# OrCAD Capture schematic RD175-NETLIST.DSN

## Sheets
1 5: size A3
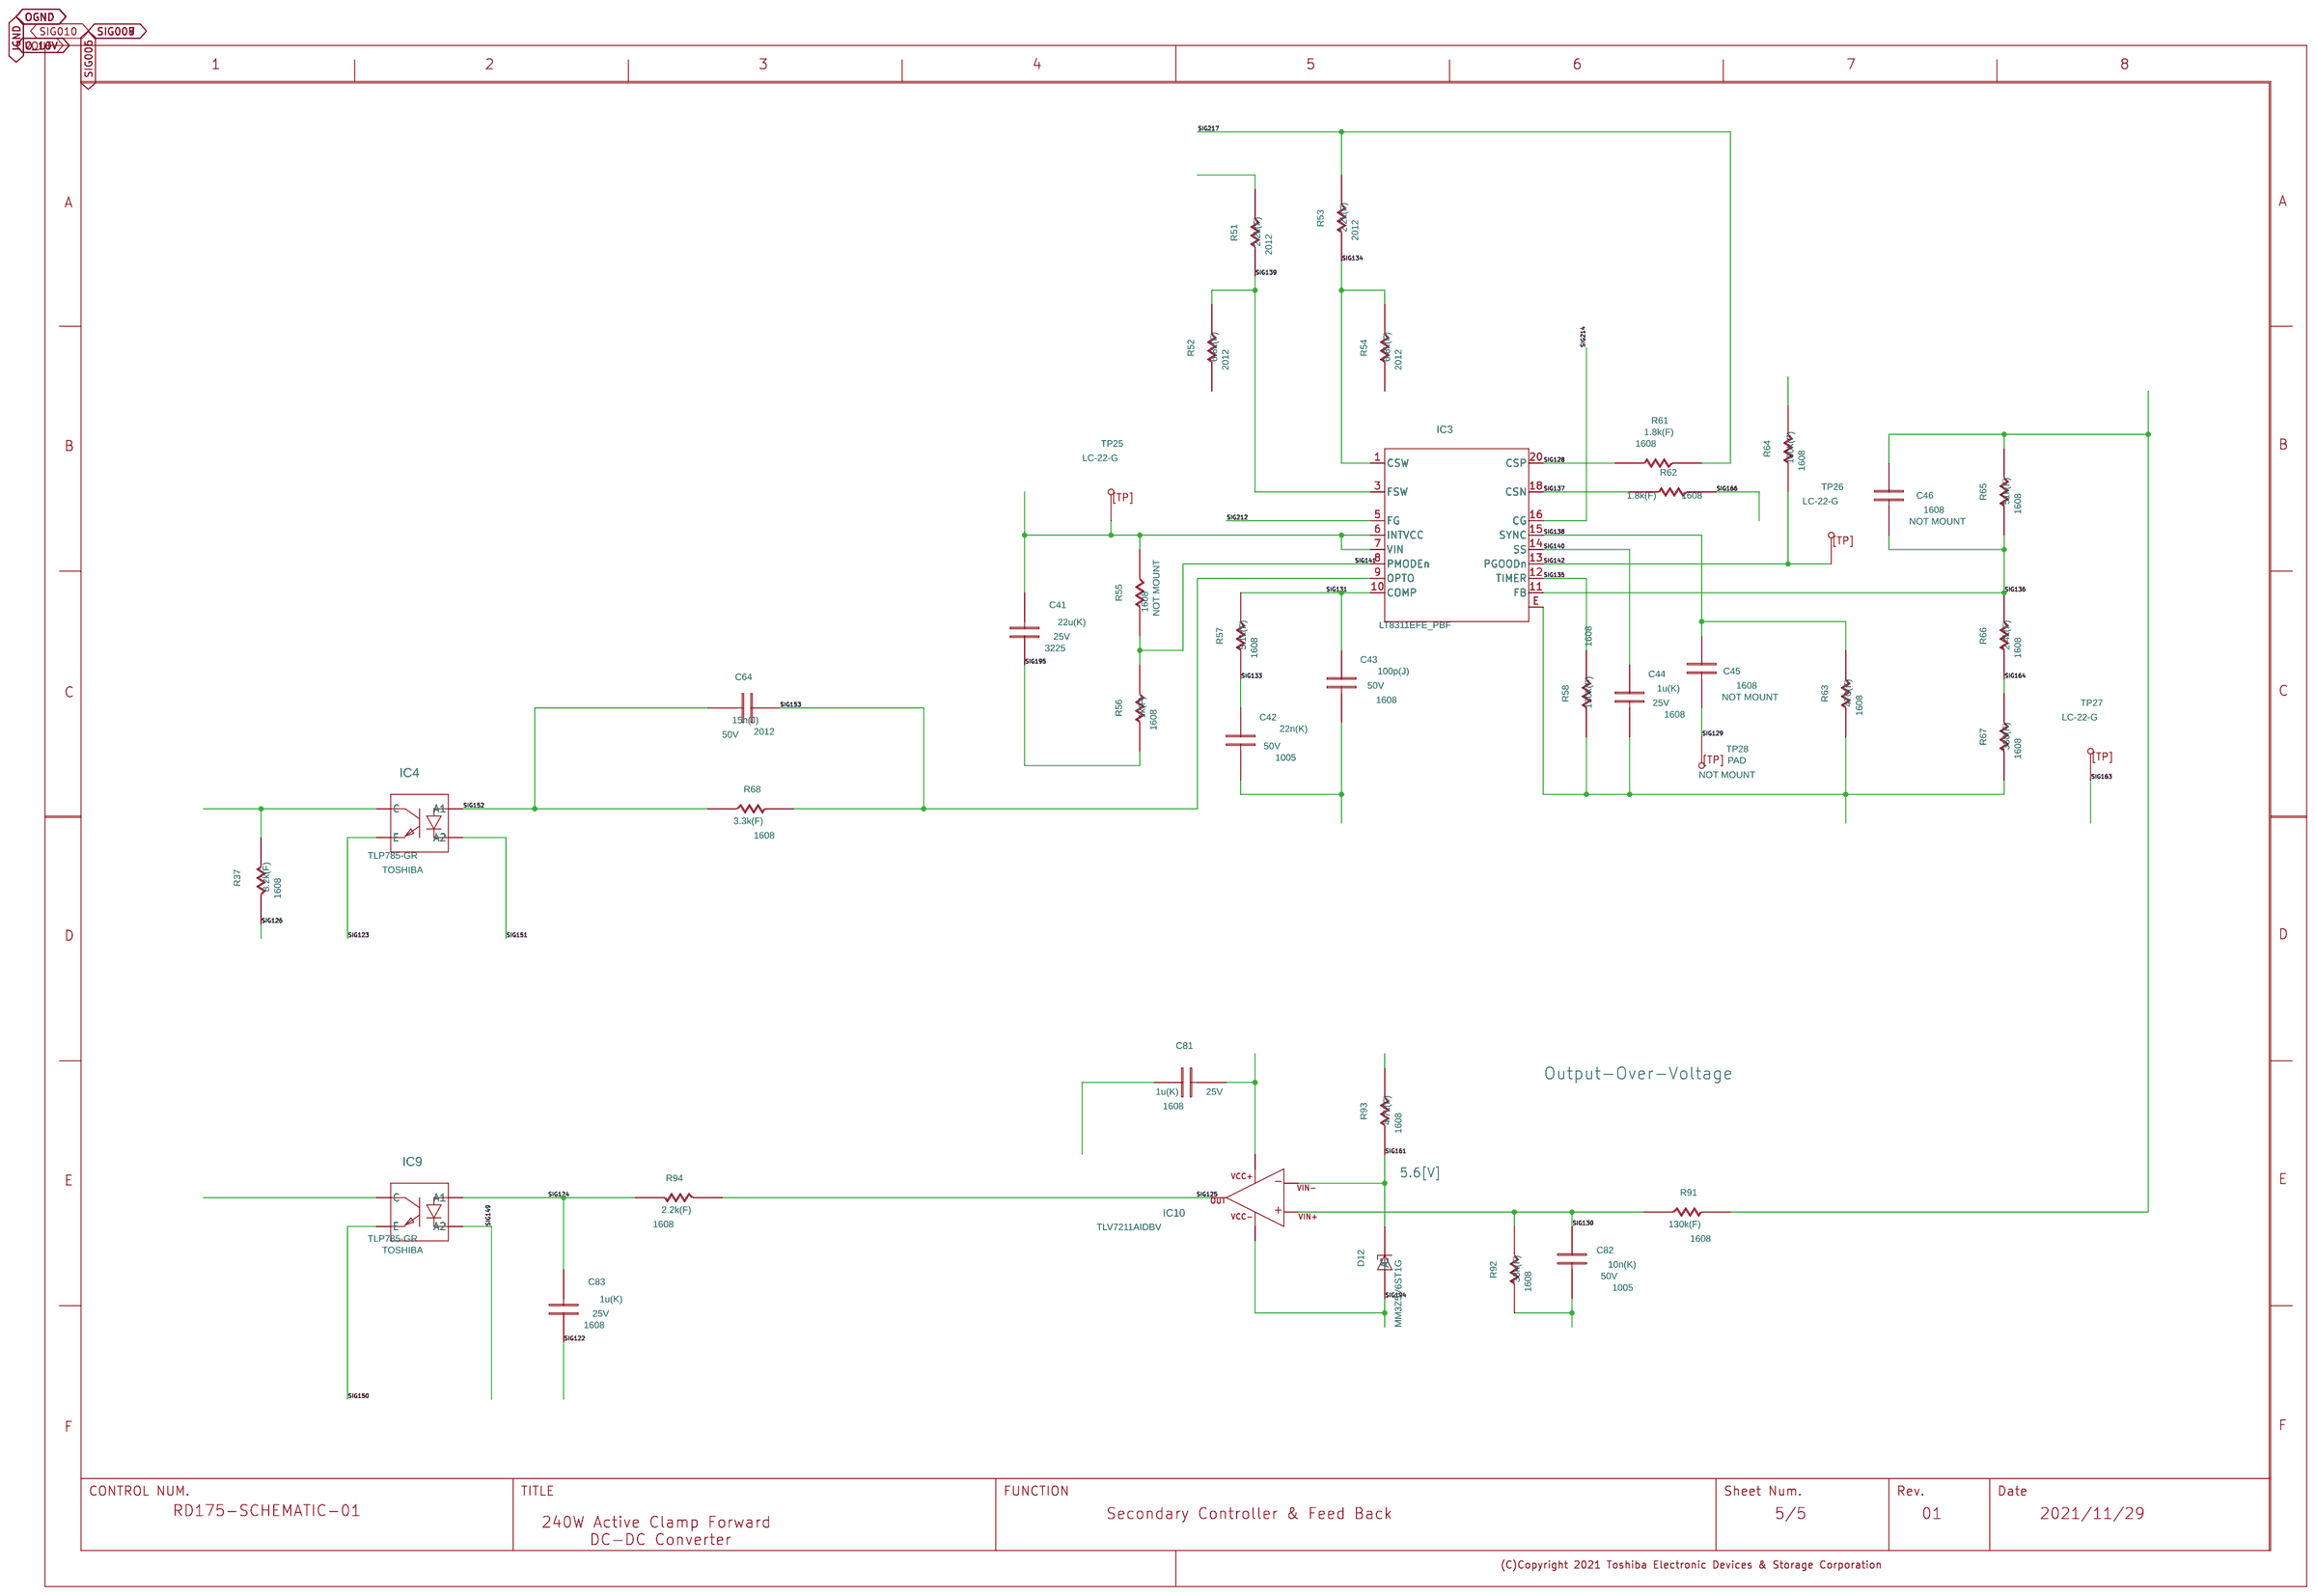
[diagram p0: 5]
2 4: size A3
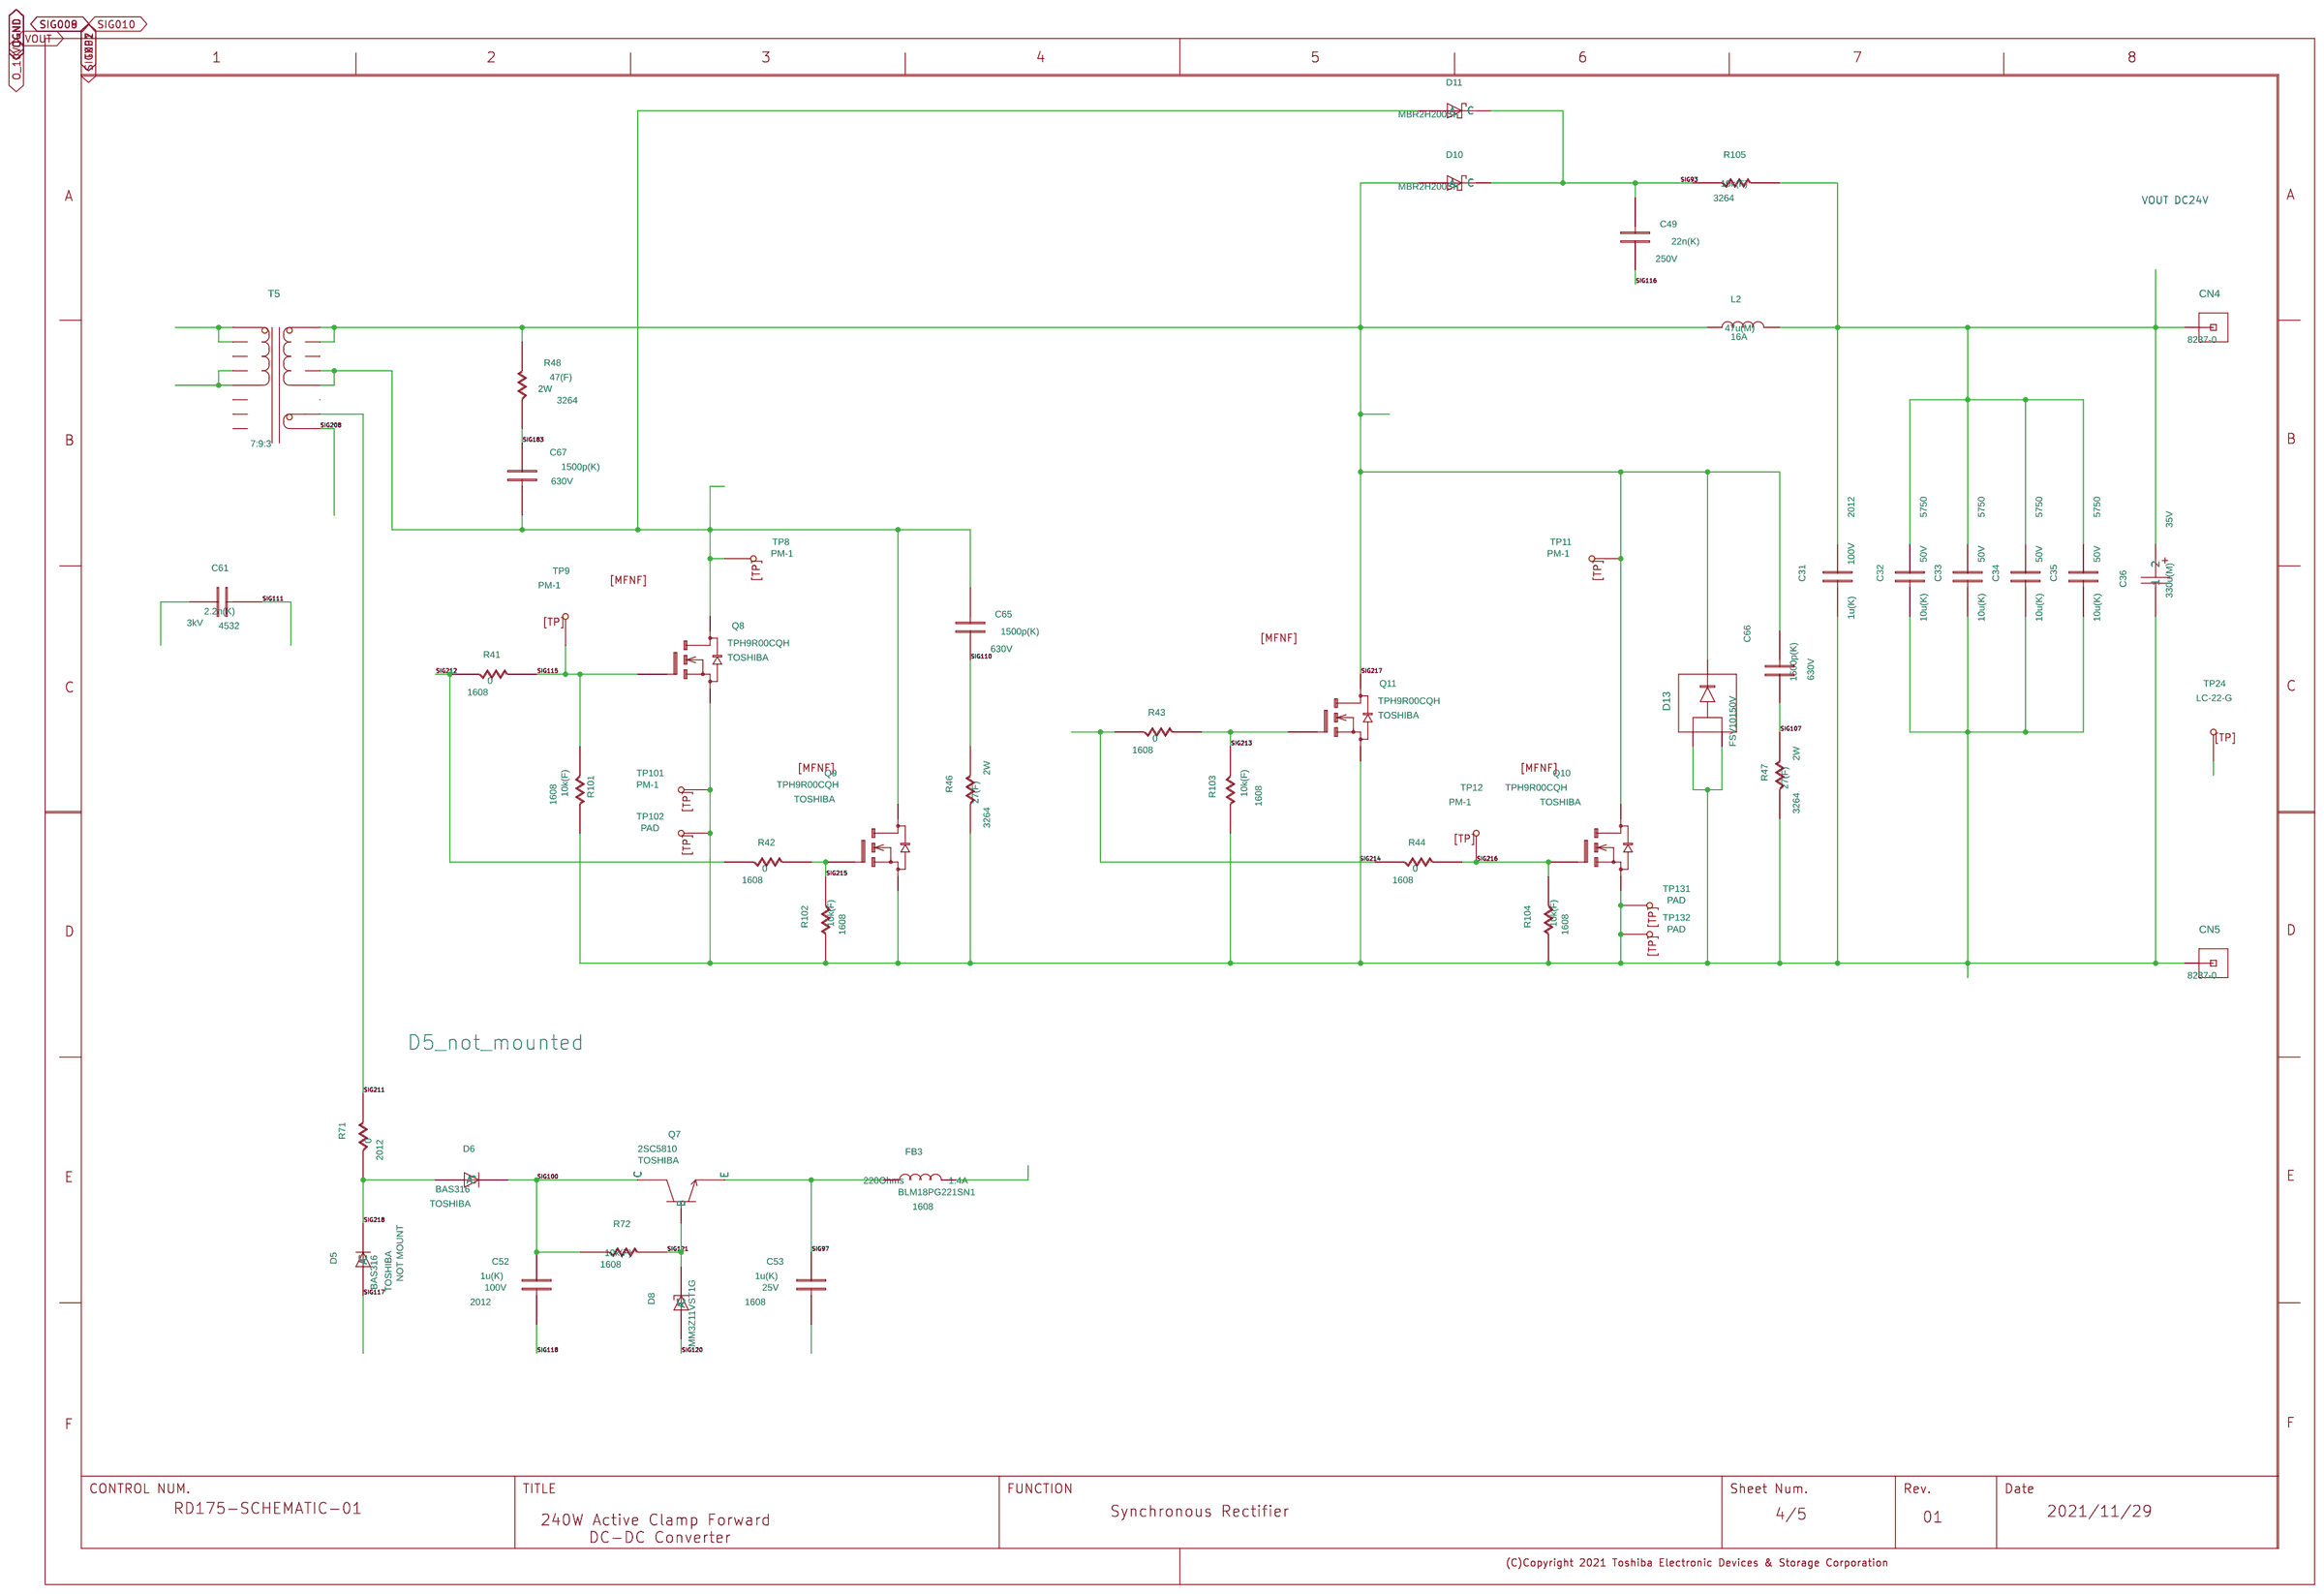
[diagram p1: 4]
3 3: size A3
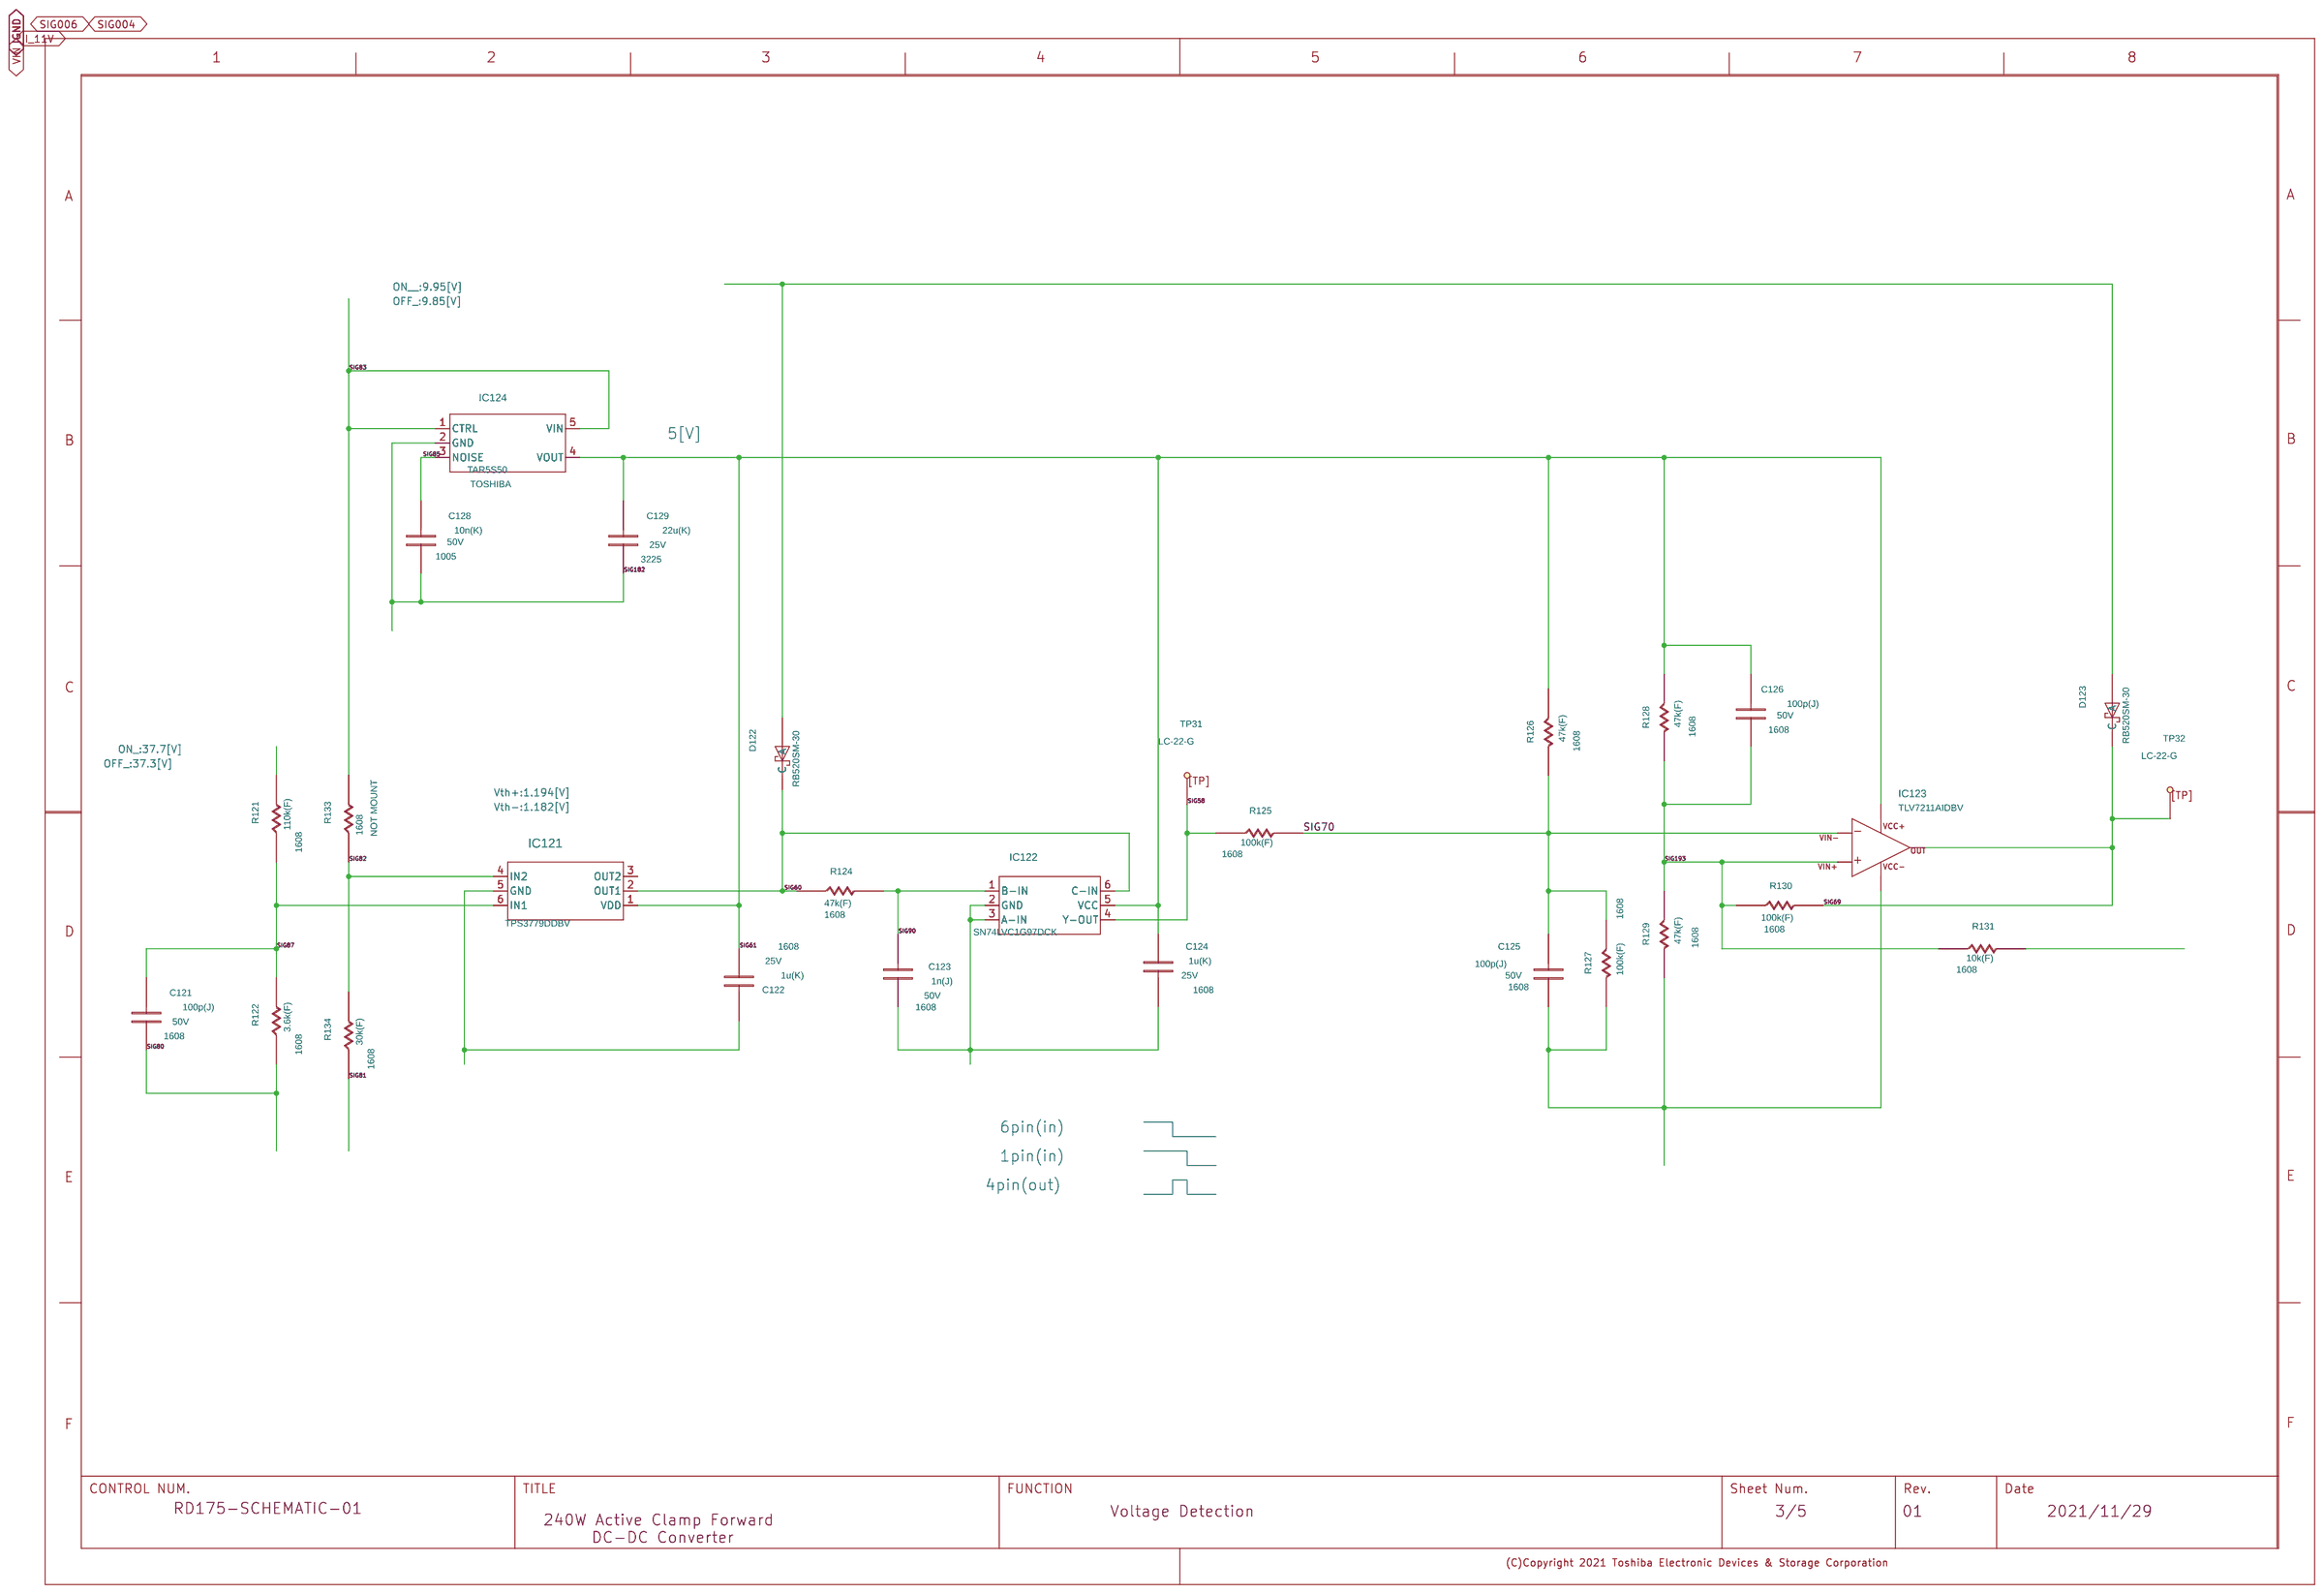
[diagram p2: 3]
4 2: size A3
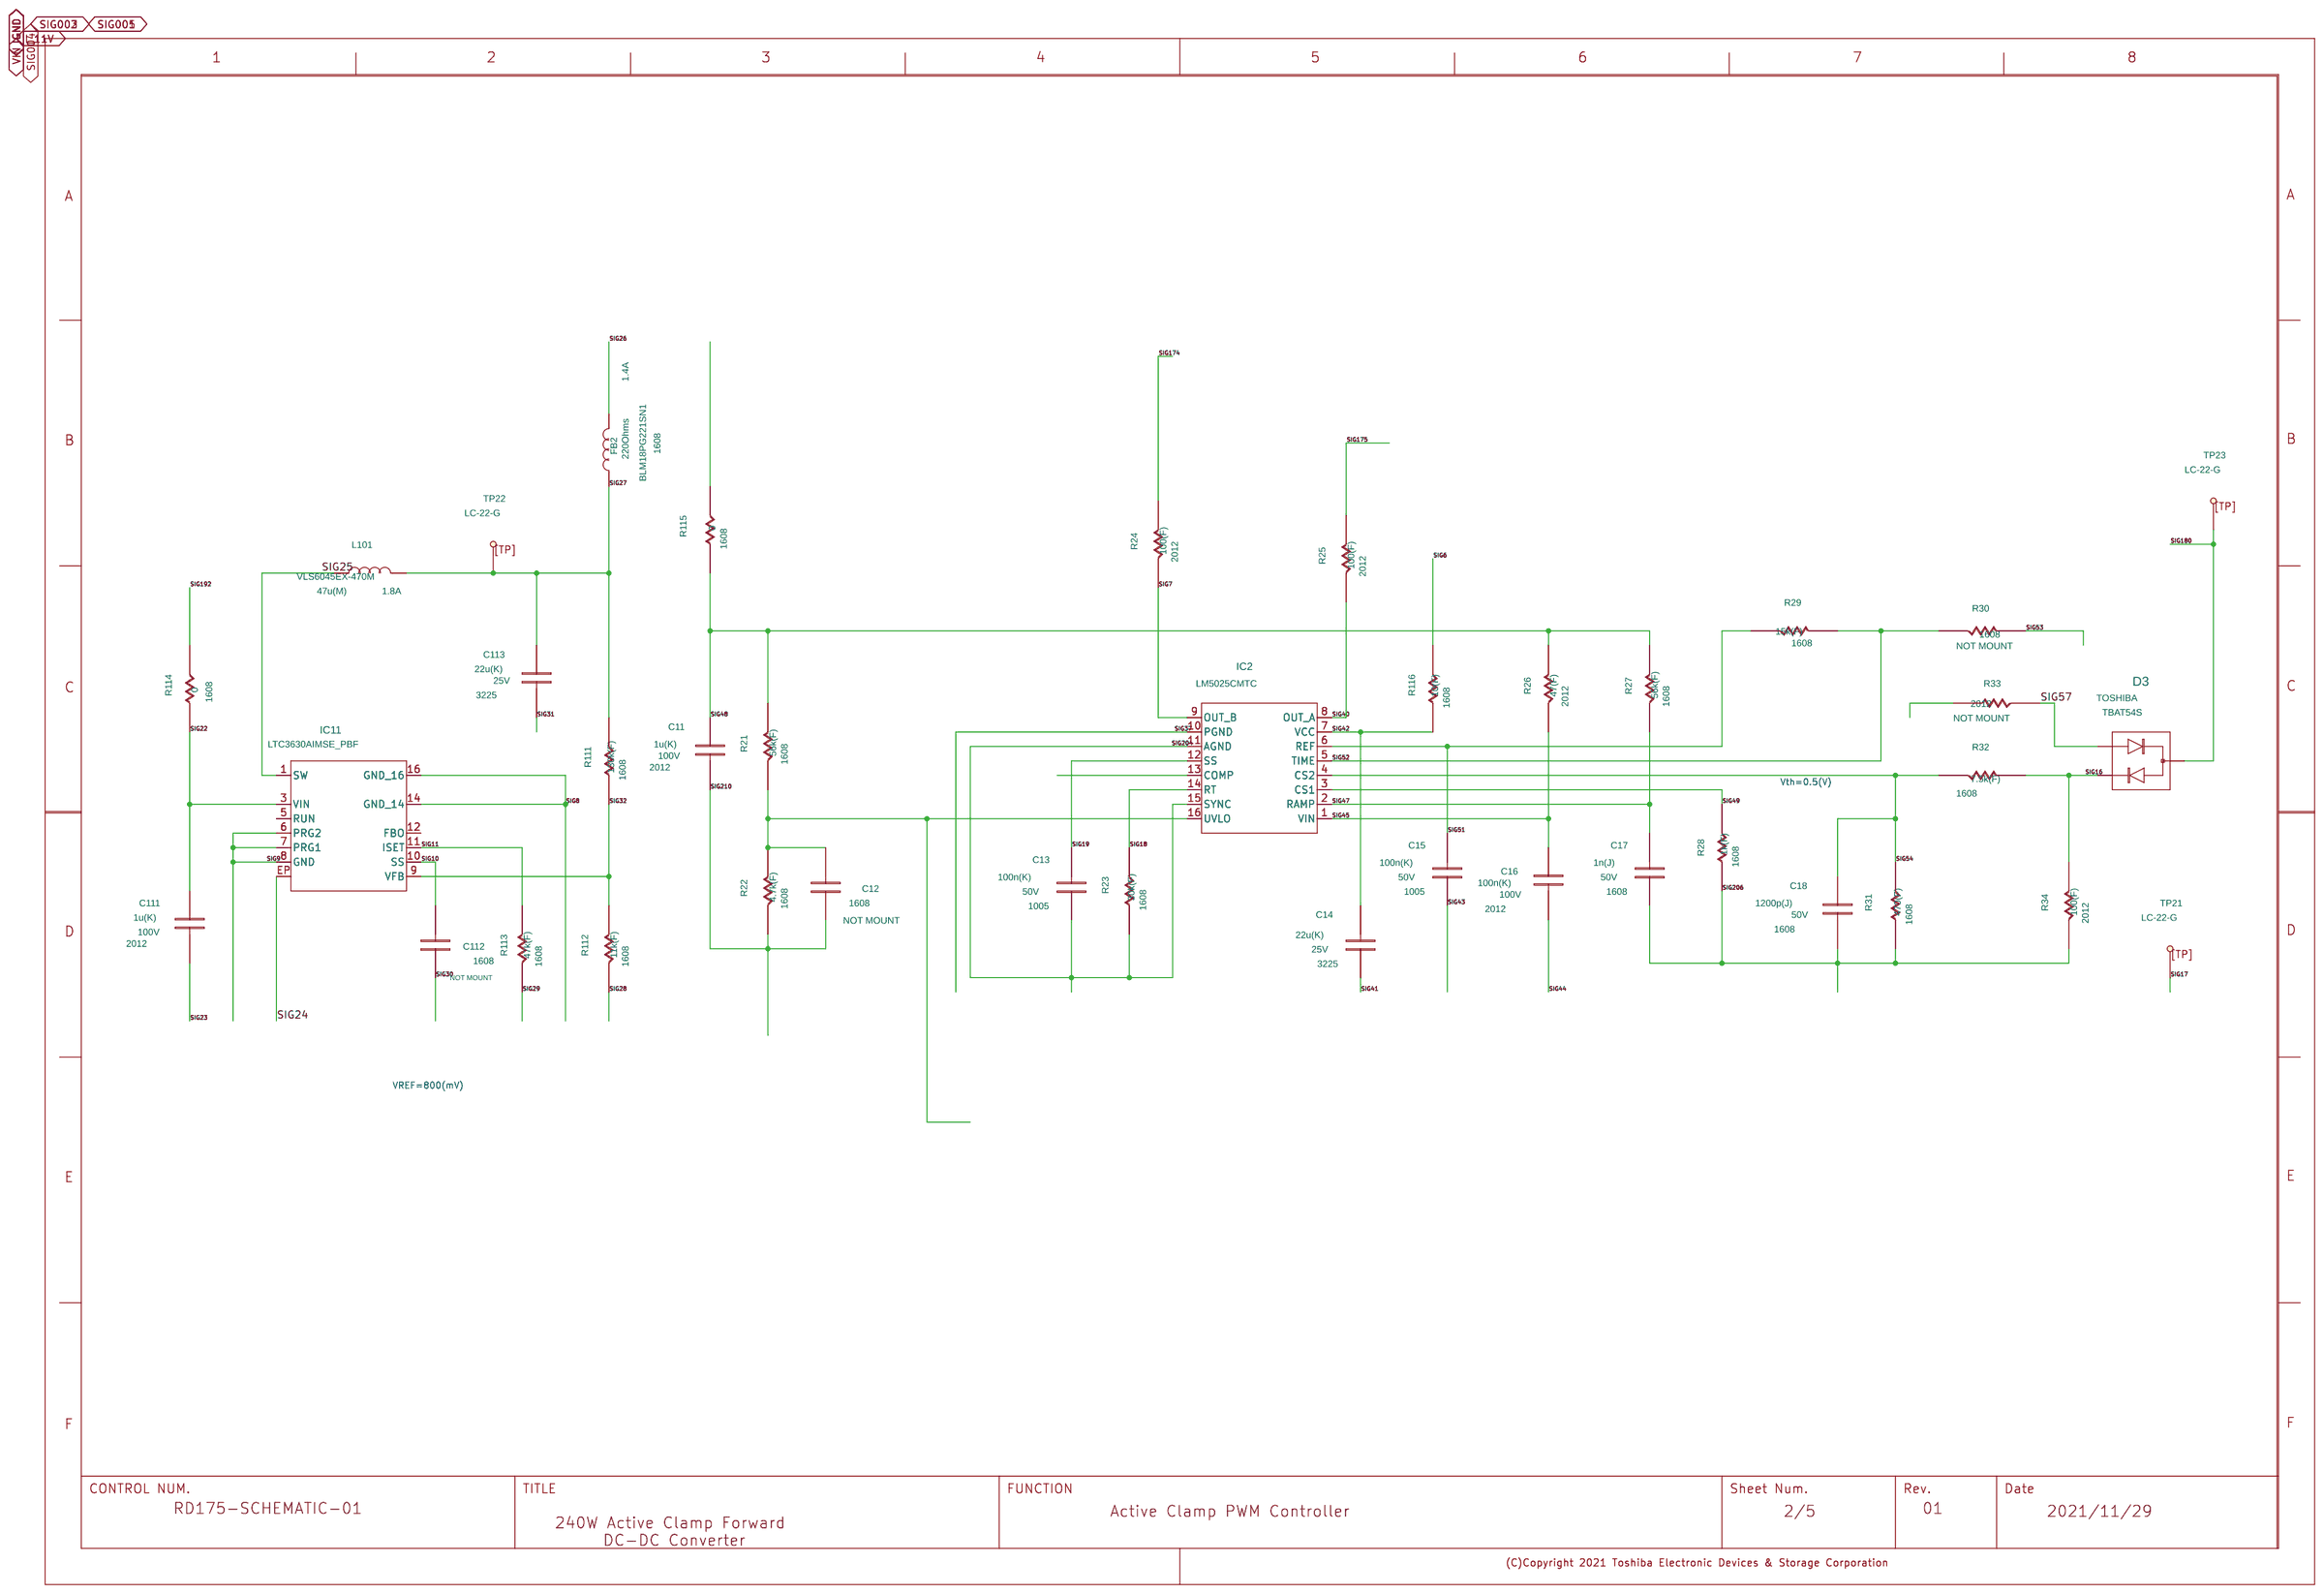
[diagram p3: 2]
5 1: size A3
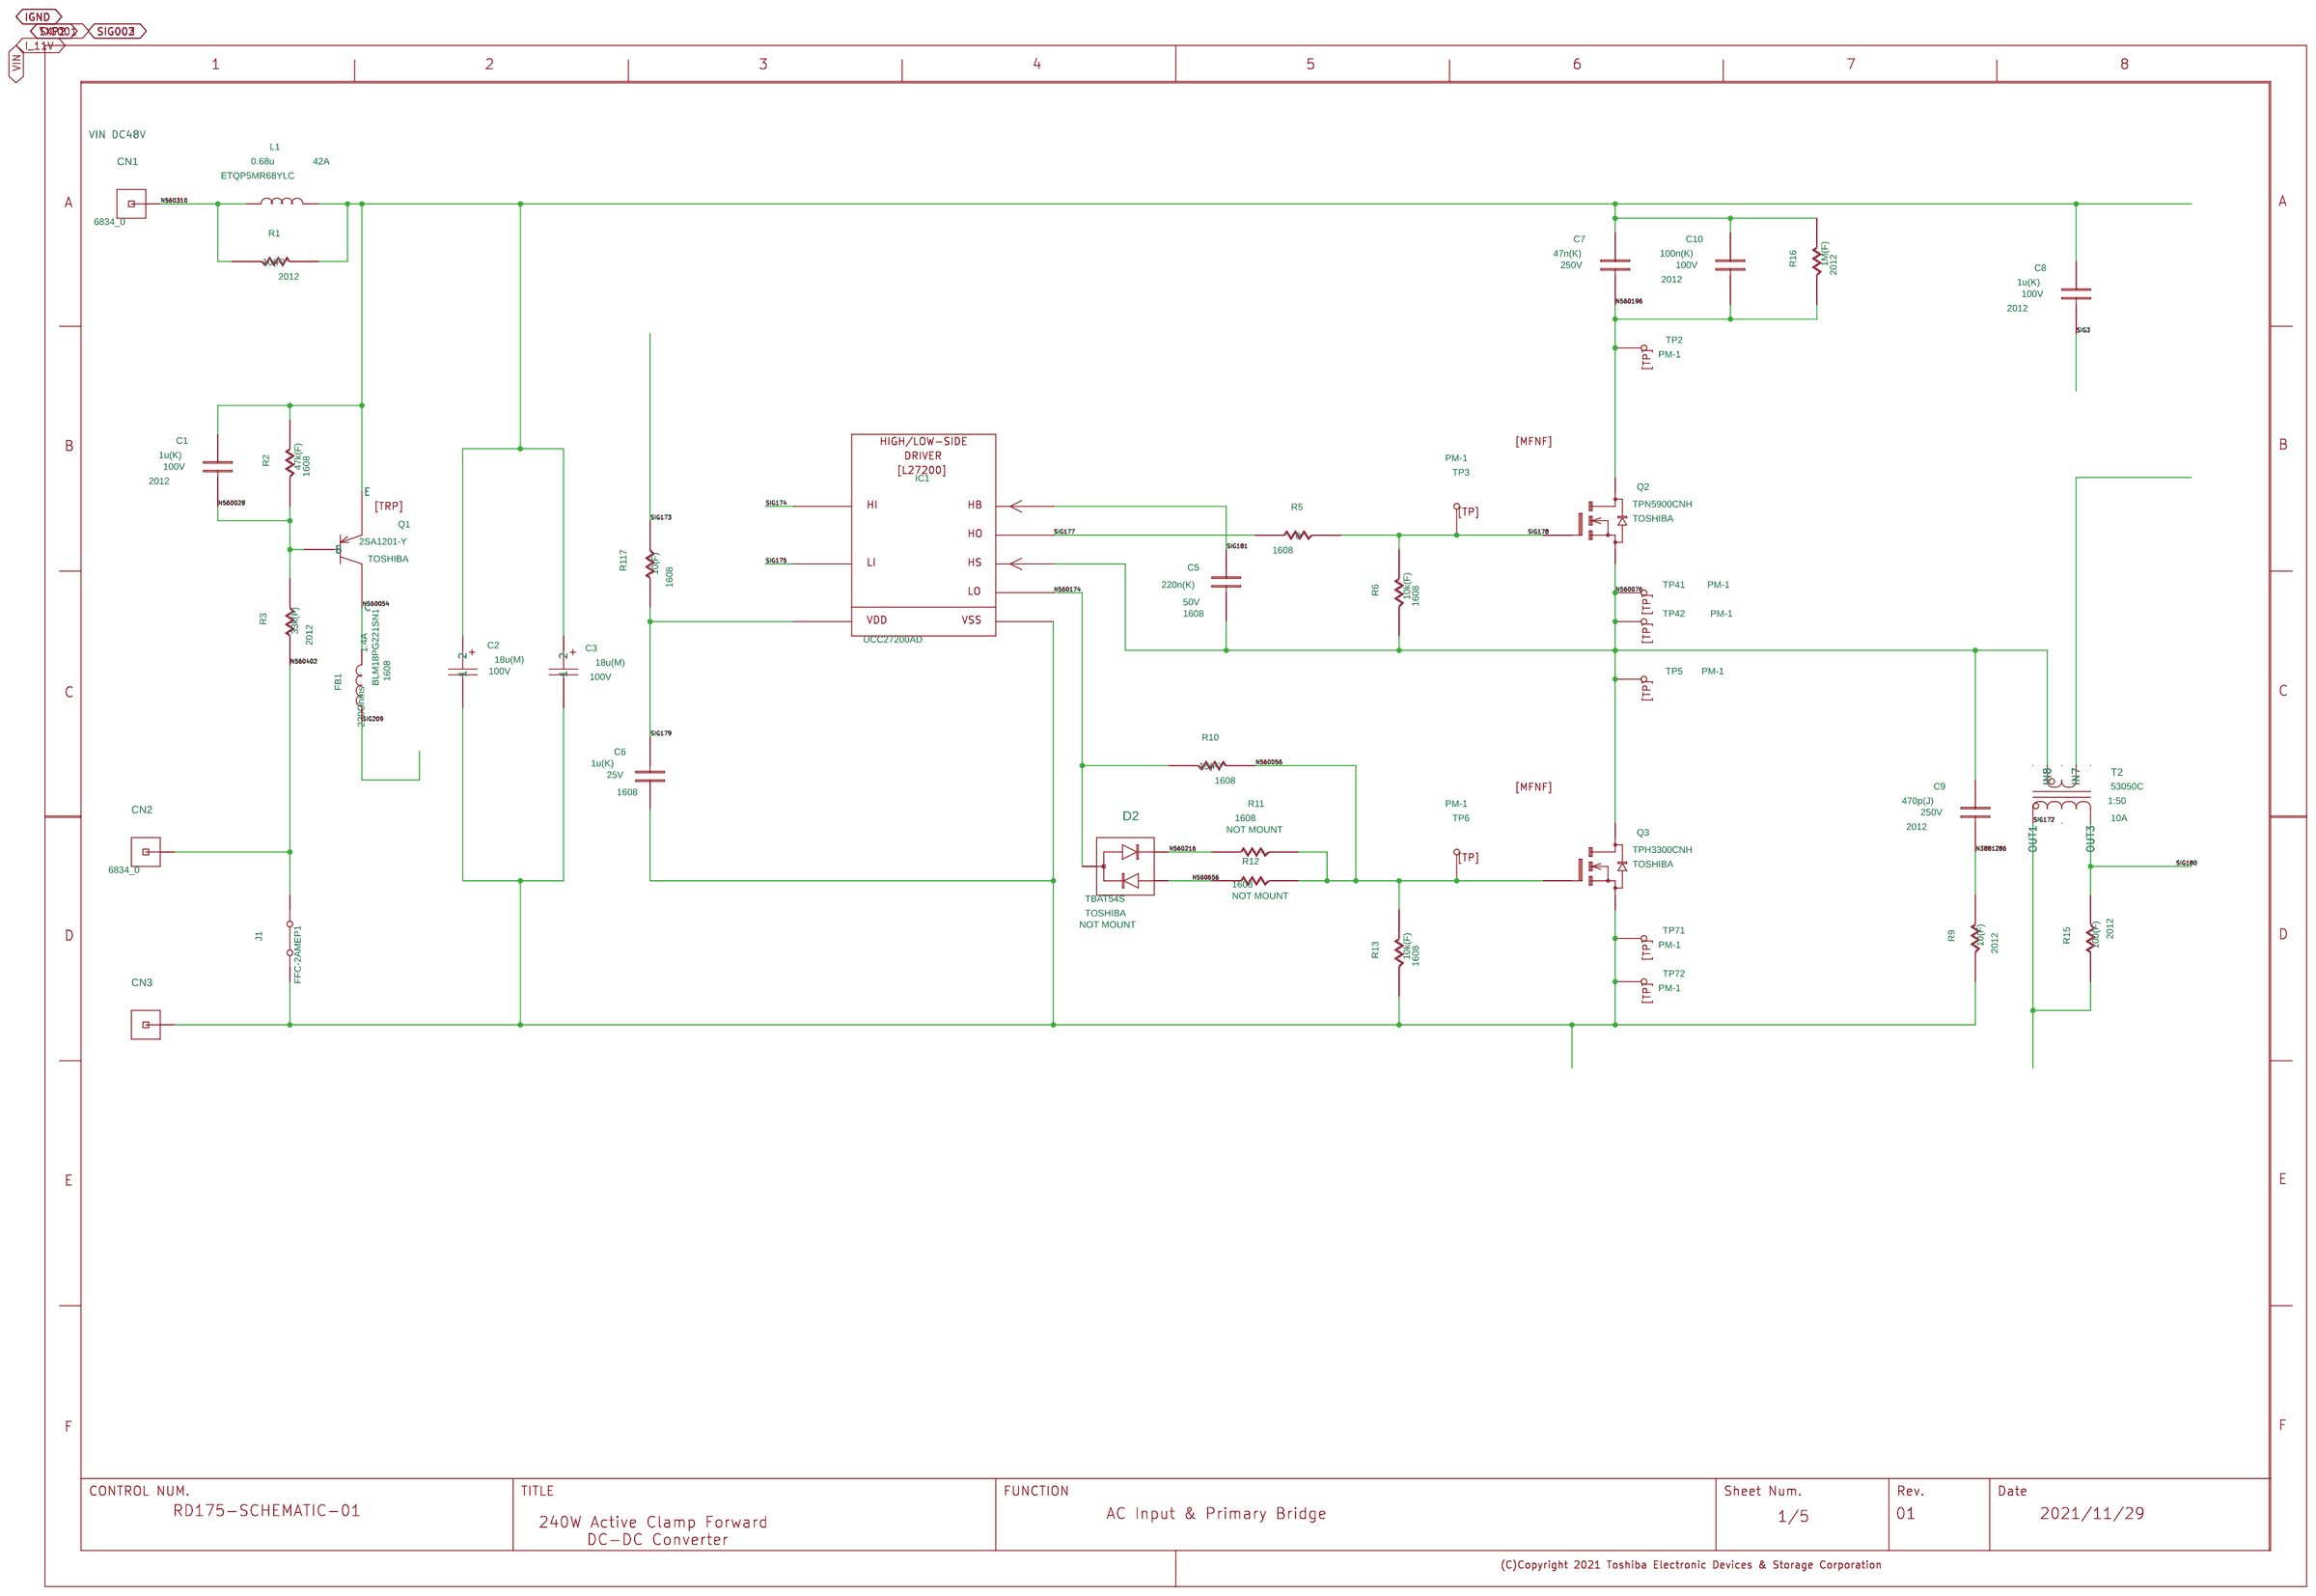
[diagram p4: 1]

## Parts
sheet 1
C1  C
C2  CP
C3  CP
C5  C
C6  C
C7  C
C8  C
C9  C
C10  C
CN1  6834-0  [TH-1]
CN2  6834-0  [TH-1]
CN3  6834-0  [TH-1]
D2  NM_TBAT54S  [SOT23-3]
FB1  L
IC1  L27200
J1  JP
L1  L
Q1  TRP
Q2  MFNF
Q3  MFNF
R1  R
R2  R
R3  R
R5  R
R6  R
R9  R
R10  R
R11  R
R12  R
R13  R
R15  R
R16  R
R117  R
T2  AF_TRANS_2B_MURATA_
TP2  TP
TP3  TP
TP5  TP
TP6  TP
TP41  TP
TP42  TP
TP71  TP
TP72  TP
U?#4  WAKU_DEF100
sheet 2
C11  C
C12  C
C13  C
C14  C
C15  C
C16  C
C17  C
C18  C
C111  C
C112  C
C113  C
D3  NM_TBAT54S  [SOT23-3]
FB2  L
IC2  LM5025C
IC11  LTC3630A
L101  L
R21  R
R22  R
R23  R
R24  R
R25  R
R26  R
R27  R
R28  R
R29  R
R30  R
R31  R
R32  R
R33  R
R34  R
R111  R
R112  R
R113  R
R114  R
R115  R
R116  R
TP21  TP
TP22  TP
TP23  TP
U?#3  WAKU_DEF100
sheet 3
C121  C
C122  C
C123  C
C124  C
C125  C
C126  C
C128  C
C129  C
D122  SBD
D123  SBD
IC121  TPS3779DDBV  [SOT23-6]
IC122  SN74AUP1G97_SMALL_
IC123  TLV7211A  [SOT23-5]
IC124  TAR5S50_NEW_
R121  R
R122  R
R124  R
R125  R
R126  R
R127  R
R128  R
R129  R
R130  R
R131  R
R133  R
R134  R
TP31  TP
TP32  TP
U?#2  WAKU_DEF100
sheet 4
C31  C
C32  C
C33  C
C34  C
C35  C
C36  CP
C49  C
C52  C
C53  C
C61  C
C65  C
C66  C
C67  C
CN4  8237-0  [TH-1]
CN5  8237-0  [TH-1]
D5  D
D6  D
D8  ZD
D10  SBD
D11  SBD
D13  Diode
FB3  L
L2  L
Q7  TRN
Q8  MFNF
Q9  MFNF
Q10  MFNF
Q11  MFNF
R41  R
R42  R
R43  R
R44  R
R46  R
R47  R
R48  R
R71  R
R72  R
R101  R
R102  R
R103  R
R104  R
R105  R
T5  AF_TRANS_4B_
TP8  TP
TP9  TP
TP11  TP
TP12  TP
TP24  TP
TP101  TP
TP102  TP
TP131  TP
TP132  TP
U?#1  WAKU_DEF100
sheet 5
C41  C
C42  C
C43  C
C44  C
C45  C
C46  C
C64  C
C81  C
C82  C
C83  C
D12  ZD
IC3  LT8311
IC4  TLP785-GR  [DIP-4]
IC9  TLP785-GR  [DIP-4]
IC10  OP_AMP_5PIN_2_
R37  R
R51  R
R52  R
R53  R
R54  R
R55  R
R56  R
R57  R
R58  R
R61  R
R62  R
R63  R
R64  R
R65  R
R66  R
R67  R
R68  R
R91  R
R92  R
R93  R
R94  R
TP25  TP
TP26  TP
TP27  TP
TP28  TP
U?#5  WAKU_DEF100

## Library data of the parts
C1 C8 C11 C31 C52 C111 = C: CDBNAME: Chip2012_GS_1; COMP: Chip2012_GS_1; COMPONENTTYPE: 4; SIZECODESMD: 2012; VAL1: 1u(K); VAL2: 100V
C2 C3 = CP: CDBNAME: PCV2A180MCL1_NC; COMP: PCV2A180MCL1_NC; COMPONENTTYPE: 4; VAL1: 18u(M); VAL2: 100V
C5 = C: CDBNAME: Chip1608_GS_1; COMP: Chip1608_GS_1; COMPONENTTYPE: 4; SIZECODESMD: 1608; VAL1: 220n(K); VAL2: 50V
C6 = C: CDBNAME: Chip1608_GS_1; COMP: Chip1608_GS_1; COMPONENTTYPE: 4; OLDCOMPONENTID: 311; SIZECODESMD: 1608; VAL1: 1u(K); VAL2: 25V
C7 = C: CDBNAME: ECQE2224*F_PN; COMP: ECQE2224*F_PN; COMPONENTTYPE: 4; VAL1: 47n(K); VAL2: 250V
C9 = C: CDBNAME: Chip2012_GS_1; COMP: Chip2012_GS_1; COMPONENTTYPE: 4; SIZECODESMD: 2012; VAL1: 470p(J); VAL2: 250V
C10 C16 = C: CDBNAME: Chip2012_GS_1; COMP: Chip2012_GS_1; COMPONENTTYPE: 4; SIZECODESMD: 2012; VAL1: 100n(K); VAL2: 100V
CN1 CN2 = TESTPIN_SHORT: CDBNAME: 6834-0-00-**-00-00-03-0_ML; COMMENT: Press-fit-Pin; COMP: 6834-0-00-**-00-00-03-0_ML; COMPONENTTYPE: 4; INSTANCENAME: I582755; MAKER: Mill-Max; SAVECOUNT: 1; TYPE: 6834-0-00-15-00-00-03-0; UPDATEDATE: 2021/11/09; UPDATETIME: 20:28:41; VAL1: 6834_0; VAL3: 6834_0
CN3 = TESTPIN_SHORT: CDBNAME: 6834-0-00-**-00-00-03-0_ML; COMMENT: Press-fit-Pin; COMP: 6834-0-00-**-00-00-03-0_ML; COMPONENTTYPE: 4; INSTANCENAME: I580723; MAKER: Mill-Max; SAVECOUNT: 1; TYPE: 6834-0-00-15-00-00-03-0; UPDATEDATE: 2021/11/09; UPDATETIME: 20:28:41; VAL1: 6834_0; VAL3: 6834_0
D2 = 1SS226: CDBNAME: TBAT54S_TS; COMMENT: Schottky-barrier-diode(Dual,30V200mA); COMP: TBAT54S_TS; COMPONENTTYPE: 4; INSTANCENAME: I582211; MAKER: Toshiba; MOUNT: n.m.; NOTMOUNT: NOT MOUNT; TYPE: TBAT54S; USERCOMPTEXT3: TOSHIBA; VAL1: TBAT54S; VAL3: TBAT54S
FB1-FB3 = L: CDBNAME: Chip1608_GS_1; COMP: Chip1608_GS_1; COMPONENTTYPE: 4; SIZECODESMD: 1608; VAL1: 220Ohms; VAL2: 1.4A; VAL3: BLM18PG221SN1
IC1 = L27200: CDBNAME: UCC272**AD_TI; COMP: UCC272**AD_TI; COMPONENTTYPE: 4; VAL1: UCC27200AD; VAL3: UCC27200AD
J1 = JP: CDBNAME: FFC-2AMEP1_HN; COMP: FFC-2AMEP1_HN; COMPONENTTYPE: 4; VAL1: FFC-2AMEP1; VAL3: FFC-2AMEP1
L1 = L: CDBNAME: ETQP5M***YLC_PN; COMP: ETQP5M***YLC_PN; COMPONENTTYPE: 4; VAL1: 0.68u; VAL2: 42A; VAL3: ETQP5MR68YLC
Q1 = TRP: CDBNAME: 2SA1201_TS; COMP: 2SA1201_TS; COMPONENTTYPE: 4; USERCOMPTEXT3: TOSHIBA; VAL1: 2SA1201-Y; VAL3: 2SA1201-Y
Q2 = MFNF: CDBNAME: TPN5900CNH_TS; COMP: TPN5900CNH_TS; COMPONENTTYPE: 4; USERCOMPTEXT3: TOSHIBA; VAL1: TPN5900CNH; VAL3: TPN5900CNH
Q3 = MFNF: CDBNAME: TPH3300CNH_TS_A; COMP: TPH3300CNH_TS_A; COMPONENTTYPE: 4; USERCOMPTEXT3: TOSHIBA; VAL1: TPH3300CNH; VAL3: TPH3300CNH
R1 R9 = R: CDBNAME: Chip2012_GS_2; COMP: Chip2012_GS_2; COMPONENTTYPE: 4; SIZECODESMD: 2012; VAL1: 10(F); VAL2: 400mW
R2 R113 R126 R128 R129 = R: CDBNAME: Chip1608_GS_1; COMP: Chip1608_GS_1; COMPONENTTYPE: 4; SIZECODESMD: 1608; VAL1: 47k(F); VAL2: 100mW
R3 = R: CDBNAME: Chip2012_GS_2; COMP: Chip2012_GS_2; COMPONENTTYPE: 4; SIZECODESMD: 2012; VAL1: 33k(F); VAL2: 400mW
R5 R41-R44 R114 R115 = R: CDBNAME: Chip1608_GS_1; COMP: Chip1608_GS_1; COMPONENTTYPE: 4; SIZECODESMD: 1608; VAL1: 0
R6 R13 R72 R101-R104 R131 = R: CDBNAME: Chip1608_GS_1; COMP: Chip1608_GS_1; COMPONENTTYPE: 4; SIZECODESMD: 1608; VAL1: 10k(F); VAL2: 100mW
R10 = R: CDBNAME: Chip1608_GS_1; COMP: Chip1608_GS_1; COMPONENTTYPE: 4; SIZECODESMD: 1608; VAL1: 15(F); VAL2: 100mW
R11 R12 = R: CDBNAME: Chip1608_GS_1; COMP: Chip1608_GS_1; COMPONENTTYPE: 4; NOTMOUNT: NOT MOUNT; SIZECODESMD: 1608; VAL1: 10(F); VAL2: 100mW
R15 R24 R25 R34 = R: CDBNAME: Chip2012_GS_2; COMP: Chip2012_GS_2; COMPONENTTYPE: 4; SIZECODESMD: 2012; VAL1: 100(F); VAL2: 400mW
R16 = R: CDBNAME: Chip2012_GS_2; COMP: Chip2012_GS_2; COMPONENTTYPE: 4; SIZECODESMD: 2012; VAL1: 1M(F); VAL2: 400mW
R116 R117 = R: CDBNAME: Chip1608_GS_1; COMP: Chip1608_GS_1; COMPONENTTYPE: 4; SIZECODESMD: 1608; VAL1: 10(F); VAL2: 100mW
T2 = AF_TRANS_2B_MURATA: CDBNAME: 53***C_MU; COMP: 53***C_MU; COMPONENTTYPE: 4; SAVEAREA0: -37891,-23575,42821,13630; SAVECOUNT: 2; UPDATEDATE: 2021/11/16; UPDATETIME: 15:26:59; VAL1: 1:50; VAL2: 10A; VAL3: 53050C
TP2 TP3 TP5 TP6 TP8 TP9 TP11 TP12 TP41 TP42 TP71 TP72 TP101 = TP: CDBNAME: TP_I_TH0.7_LC1.1_RC1.2_GS; COMP: TP_I_TH0.7_LC1.1_RC1.2_GS; COMPONENTTYPE: 4; VAL1: PM-1; VAL3: PM-1
U?#4 = WAKU_DEF100: COMPONENTTYPE: 2; DATE: 2021/11/29; DRAWINGNUMBER: RD175-SCHEMATIC-01; FUNCTION: AC Input & Primary Bridge; REVISION: 01; SHEETNUMBER: 1/5; TITLE: 240W Active Clamp Forward / DC-DC Converter; UPDATEDATE: 2021/11/29; UPDATETIME: 13:17:36
C12 C112 = C: CDBNAME: Chip1608_GS_1; COMP: Chip1608_GS_1; COMPONENTTYPE: 4; NOTMOUNT: NOT MOUNT; SIZECODESMD: 1608; VAL1: 1n(J); VAL2: 50V
C13 C15 = C: CDBNAME: Chip1005_GS_2; COMP: Chip1005_GS_2; COMPONENTTYPE: 4; SIZECODESMD: 1005; VAL1: 100n(K); VAL2: 50V
C14 C41 C113 C129 = C: CDBNAME: Chip3225_GS; COMP: Chip3225_GS; COMPONENTTYPE: 4; SIZECODESMD: 3225; VAL1: 22u(K); VAL2: 25V
C17 C123 = C: CDBNAME: Chip1608_GS_1; COMP: Chip1608_GS_1; COMPONENTTYPE: 4; SIZECODESMD: 1608; VAL1: 1n(J); VAL2: 50V
C18 = C: CDBNAME: Chip1608_GS_1; COMP: Chip1608_GS_1; COMPONENTTYPE: 4; SIZECODESMD: 1608; VAL1: 1200p(J); VAL2: 50V
D3 = 1SS226: CDBNAME: TBAT54S_TS; COMMENT: Schottky-barrier-diode(Dual,30V200mA); COMP: TBAT54S_TS; COMPONENTTYPE: 4; INSTANCENAME: I582211; MAKER: Toshiba; MOUNT: n.m.; TYPE: TBAT54S; USERCOMPTEXT3: TOSHIBA; VAL1: TBAT54S; VAL3: TBAT54S
IC2 = LM5025C: CDBNAME: LM5025CMTC_GS; COMP: LM5025CMTC_GS; COMPONENTTYPE: 4; SAVEAREA0: -6985,-23317,26564,1279; SAVECOUNT: 2; UPDATEDATE: 2021/11/12; UPDATETIME: 11:19:07; VAL1: LM5025CMTC; VAL3: LM5025CMTC
IC11 = LTC3630A: CDBNAME: LTC3630AIM_LT_1; COMP: LTC3630AIM_LT_1; COMPONENTTYPE: 4; VAL1: LTC3630AIMSE_PBF; VAL3: LTC3630AIMSE_PBF
L101 = L: CDBNAME: VLS6045EX_TD; COMP: VLS6045EX_TD; COMPONENTTYPE: 4; VAL1: 47u(M); VAL2: 1.8A; VAL3: VLS6045EX-470M
R21 R27 = R: CDBNAME: Chip1608_GS_1; COMP: Chip1608_GS_1; COMPONENTTYPE: 4; SIZECODESMD: 1608; VAL1: 56k(F); VAL2: 100mW
R22 R93 = R: CDBNAME: Chip1608_GS_1; COMP: Chip1608_GS_1; COMPONENTTYPE: 4; SIZECODESMD: 1608; VAL1: 4.7k(F); VAL2: 100mW
R23 R134 = R: CDBNAME: Chip1608_GS_1; COMP: Chip1608_GS_1; COMPONENTTYPE: 4; SIZECODESMD: 1608; VAL1: 30k(F); VAL2: 100mW
R26 = R: CDBNAME: Chip2012_GS_2; COMP: Chip2012_GS_2; COMPONENTTYPE: 4; SIZECODESMD: 2012; VAL1: 47(F); VAL2: 400mW
R28 R56 = R: CDBNAME: Chip1608_GS_1; COMP: Chip1608_GS_1; COMPONENTTYPE: 4; SIZECODESMD: 1608; VAL1: 1k(F); VAL2: 100mW
R29 = R: CDBNAME: Chip1608_GS_1; COMP: Chip1608_GS_1; COMPONENTTYPE: 4; SIZECODESMD: 1608; VAL1: 15k(F); VAL2: 100mW
R30 = R: CDBNAME: Chip1608_GS_1; COMP: Chip1608_GS_1; COMPONENTTYPE: 4; NOTMOUNT: NOT MOUNT; SIZECODESMD: 1608; VAL1: 15k(F); VAL2: 100mW
R31 R63 = R: CDBNAME: Chip1608_GS_1; COMP: Chip1608_GS_1; COMPONENTTYPE: 4; SIZECODESMD: 1608; VAL1: 470(F); VAL2: 100mW
R32 = R: CDBNAME: Chip1608_GS_1; COMP: Chip1608_GS_1; COMPONENTTYPE: 4; SIZECODESMD: 1608; VAL1: 7.5k(F); VAL2: 100mW
R33 = R: CDBNAME: Chip2012_GS_2; COMP: Chip2012_GS_2; COMPONENTTYPE: 4; NOTMOUNT: NOT MOUNT; SIZECODESMD: 2012; VAL1: 100(F); VAL2: 400mW
R58 R91 R111 = R: CDBNAME: Chip1608_GS_1; COMP: Chip1608_GS_1; COMPONENTTYPE: 4; SIZECODESMD: 1608; VAL1: 130k(F); VAL2: 100mW
R112 = R: CDBNAME: Chip1608_GS_1; COMP: Chip1608_GS_1; COMPONENTTYPE: 4; SIZECODESMD: 1608; VAL1: 11k(F); VAL2: 100mW
TP21-TP27 TP31 TP32 = TP: CDBNAME: LC-22_GS; COMP: LC-22_GS; COMPONENTTYPE: 4; VAL1: LC-22-G; VAL3: LC-22-G
U?#3 = WAKU_DEF100: AUTHOR: t5459927; COMPONENTTYPE: 2; DATE: 2021/11/29; DRAWINGNUMBER: RD175-SCHEMATIC-01; FUNCTION: Active Clamp PWM Controller; REVISION: 01; SAVEAREA0: -45080,-4508,463680,304612; SHEETNUMBER: 2/5; TIME: 14:24:20; TITLE: 240W Active Clamp Forward / DC-DC Converter; UPDATEDATE: 2021/11/29; UPDATETIME: 13:11:56
C43 C121 C125 C126 = C: CDBNAME: Chip1608_GS_1; COMP: Chip1608_GS_1; COMPONENTTYPE: 4; SIZECODESMD: 1608; VAL1: 100p(J); VAL2: 50V
C44 C53 C81 C83 C122 C124 = C: CDBNAME: Chip1608_GS_1; COMP: Chip1608_GS_1; COMPONENTTYPE: 4; SIZECODESMD: 1608; VAL1: 1u(K); VAL2: 25V
C82 C128 = C: CDBNAME: Chip1005_GS_2; COMP: Chip1005_GS_2; COMPONENTTYPE: 4; SIZECODESMD: 1005; VAL1: 10n(K); VAL2: 50V
D122 D123 = SBD: CDBNAME: RB520SM-30_RM; COMP: RB520SM-30_RM; COMPONENTTYPE: 4; VAL1: RB520SM-30; VAL3: RB520SM-30
IC121 = TPS3779_DBV: CDBNAME: TPS3779*DBV_TI_1; COMMENT: Voltage-detector(Dual,Push-pull_Output); COMP: TPS3779*DBV_TI_1; COMPONENTTYPE: 4; INSTANCENAME: I582549; MAKER: T.I.; SAVECOUNT: 1; UPDATEDATE: 2021/11/09; UPDATETIME: 20:28:41
IC122 = SN74AUP1G97_SMALL: CDBNAME: SN74LVC1G97DCK_TI; COMP: SN74LVC1G97DCK_TI; COMPONENTTYPE: 4; VAL1: SN74LVC1G97DCK; VAL3: SN74LVC1G97DCK
IC123 = OP_AMP_5PIN_2: CDBNAME: TLV7211AIDBVR_TI; COMMENT: Voltage-comparator(Single,R-to-R_IO); COMP: TLV7211AIDBVR_TI; COMPONENTTYPE: 4; INSTANCENAME: I581857; MAKER: T.I.; SAVECOUNT: 1; TYPE: TLV7211AIDBV; UPDATEDATE: 2021/11/09; UPDATETIME: 20:28:41; VAL1: TLV7211AIDBV; VAL3: TLV7211AIDBV
IC124 = TAR5S50_NEW: CDBNAME: TAR5S**_TS; COMP: TAR5S**_TS; COMPONENTTYPE: 4; USERCOMPTEXT3: TOSHIBA; VAL1: TAR5S50; VAL3: TAR5S50
R121 = R: CDBNAME: Chip1608_GS_1; COMP: Chip1608_GS_1; COMPONENTTYPE: 4; SIZECODESMD: 1608; VAL1: 110k(F); VAL2: 100mW
R122 = R: CDBNAME: Chip1608_GS_1; COMP: Chip1608_GS_1; COMPONENTTYPE: 4; SIZECODESMD: 1608; VAL1: 3.6k(F); VAL2: 100mW
R124 = R: CDBNAME: Chip1608_GS_1; COMP: Chip1608_GS_1; COMPONENTTYPE: 4; OLDCOMPONENTID: 68; SIZECODESMD: 1608; VAL1: 47k(F); VAL2: 100mW
R64 R125 R127 R130 = R: CDBNAME: Chip1608_GS_1; COMP: Chip1608_GS_1; COMPONENTTYPE: 4; SIZECODESMD: 1608; VAL1: 100k(F); VAL2: 100mW
R133 = R: CDBNAME: Chip1608_GS_1; COMP: Chip1608_GS_1; COMPONENTTYPE: 4; NOTMOUNT: NOT MOUNT; SIZECODESMD: 1608; VAL1: 220k(F); VAL2: 100mW
U?#2 = WAKU_DEF100: AUTHOR: t5459927; COMPONENTTYPE: 2; DATE: 2021/11/29; DRAWINGNUMBER: RD175-SCHEMATIC-01; FUNCTION: Voltage Detection; REVISION: 01; SAVEAREA0: -45080,-4508,463680,304612; SHEETNUMBER: 3/5; TIME: 17:45:19; TITLE: 240W Active Clamp Forward / DC-DC Converter; UPDATEDATE: 2021/11/29; UPDATETIME: 13:12:32
C32-C35 = C: CDBNAME: Chip5750_TD; COMP: Chip5750_TD; COMPONENTTYPE: 4; SIZECODESMD: 5750; VAL1: 10u(K); VAL2: 50V
C36 = CP: CDBNAME: EEHZS1V331P_PN; COMP: EEHZS1V331P_PN; COMPONENTTYPE: 4; VAL1: 330u(M); VAL2: 35V
C49 = C: CDBNAME: ECQE2103*B_PN; COMP: ECQE2103*B_PN; COMPONENTTYPE: 4; VAL1: 22n(K); VAL2: 250V
C61 = C: CDBNAME: Chip4632_AV; COMP: Chip4632_AV; COMPONENTTYPE: 4; SIZECODESMD: 4532; VAL1: 2.2n(K); VAL2: 3kV
C65-C67 = C: CDBNAME: ECQE6222*F_PN; COMP: ECQE6222*F_PN; COMPONENTTYPE: 4; VAL1: 1500p(K); VAL2: 630V
CN4 CN5 = TESTPIN_SHORT: CDBNAME: 8237-0-05-**-00-00-03-0_ML; COMMENT: Press-fit-Pin; COMP: 8237-0-05-**-00-00-03-0_ML; COMPONENTTYPE: 4; INSTANCENAME: I581677; MAKER: Mill-Max; SAVECOUNT: 1; TYPE: 8237-0-05-15-00-00-03-0; UPDATEDATE: 2021/11/09; UPDATETIME: 20:28:41
D5 = D: CDBNAME: BAS316_TS_A; COMP: BAS316_TS_A; COMPONENTTYPE: 4; NOTMOUNT: NOT MOUNT; USERCOMPTEXT3: TOSHIBA; VAL1: BAS316; VAL3: BAS316
D6 = D: CDBNAME: BAS316_TS_A; COMP: BAS316_TS_A; COMPONENTTYPE: 4; USERCOMPTEXT3: TOSHIBA; VAL1: BAS316; VAL3: BAS316
D8 = ZD: CDBNAME: MM3Z***ST1G_OS_A; COMP: MM3Z***ST1G_OS_A; COMPONENTTYPE: 4; VAL1: MM3Z11VST1G; VAL3: MM3Z11VST1G
D10 D11 = SBD: CDBNAME: SS220LW_TW; COMP: SS220LW_TW; COMPONENTTYPE: 4; VAL1: MBR2H200SF; VAL3: MBR2H200SF
D13 = DIODE_SINGLE_TO277_3: CDBNAME: FSV10150V_OS; COMP: FSV10150V_OS; COMPONENTTYPE: 4; VAL1: FSV10150V; VAL3: FSV10150V
L2 = L: CDBNAME: SRP1770TA_BO; COMP: SRP1770TA_BO; COMPONENTTYPE: 4; VAL1: 47u(M); VAL2: 16A; VAL3: SRP1770TA-470M
Q7 = TRN: CDBNAME: 2SC5810_TS; COMP: 2SC5810_TS; COMPONENTTYPE: 4; USERCOMPTEXT3: TOSHIBA; VAL1: 2SC5810; VAL3: 2SC5810
Q8-Q11 = MFNF: CDBNAME: TPH9R00CQH_TS_A; COMP: TPH9R00CQH_TS_A; COMPONENTTYPE: 4; USERCOMPTEXT3: TOSHIBA; VAL1: TPH9R00CQH; VAL3: TPH9R00CQH
R46 R47 = R: CDBNAME: LTR100_RM; COMP: LTR100_RM; COMPONENTTYPE: 4; SIZECODESMD: 3264; VAL1: 27(F); VAL2: 2W
R48 = R: CDBNAME: LTR100_RM; COMP: LTR100_RM; COMPONENTTYPE: 4; SIZECODESMD: 3264; VAL1: 47(F); VAL2: 2W
R71 = R: CDBNAME: Chip2012_GS_1; COMP: Chip2012_GS_1; COMPONENTTYPE: 4; SIZECODESMD: 2012; VAL1: 0
R105 = R: CDBNAME: LTR100_RM; COMP: LTR100_RM; COMPONENTTYPE: 4; SIZECODESMD: 3264; VAL1: 10k(F); VAL2: 2W
T5 = AF_TRANS_4B: CDBNAME: BEER35-1116CPHFR_GS; COMP: BEER35-1116CPHFR_GS; COMPONENTTYPE: 4; VAL1: 7:9:3
TP102 TP131 TP132 = TP: CDBNAME: TP_I_TH0.7_LC1.1_RC1.2_GS; COMP: TP_I_TH0.7_LC1.1_RC1.2_GS; COMPONENTTYPE: 4; VAL1: PAD; VAL3: PAD
U?#1 = WAKU_DEF100: AUTHOR: t5459927; COMPONENTTYPE: 2; DATE: 2021/11/29; DRAWINGNUMBER: RD175-SCHEMATIC-01; FUNCTION: Synchronous Rectifier; REVISION: 01; SAVEAREA0: -45080,-4508,463680,304612; SHEETNUMBER: 4/5; TIME: 08:38:37; TITLE: 240W Active Clamp Forward / DC-DC Converter; UPDATEDATE: 2021/11/29; UPDATETIME: 13:15:26
C42 = C: CDBNAME: Chip1005_GS_2; COMP: Chip1005_GS_2; COMPONENTTYPE: 4; SIZECODESMD: 1005; VAL1: 22n(K); VAL2: 50V
C45 = C: CDBNAME: Chip1608_GS_1; COMP: Chip1608_GS_1; COMPONENTTYPE: 4; NOTMOUNT: NOT MOUNT; SIZECODESMD: 1608; VAL1: 220p(J); VAL2: 50V
C46 = C: CDBNAME: Chip1608_GS_1; COMP: Chip1608_GS_1; COMPONENTTYPE: 4; NOTMOUNT: NOT MOUNT; SIZECODESMD: 1608; VAL1: 100p(J); VAL2: 50V
C64 = C: CDBNAME: Chip2012_GS_1; COMP: Chip2012_GS_1; COMPONENTTYPE: 4; SIZECODESMD: 2012; VAL1: 15n(J); VAL2: 50V
D12 = ZD: CDBNAME: MM3Z***ST1G_OS_A; COMP: MM3Z***ST1G_OS_A; COMPONENTTYPE: 4; VAL1: MM3Z5V6ST1G; VAL3: MM3Z5V6ST1G
IC3 = LT8311: CDBNAME: LT8311*FE_GS; COMP: LT8311*FE_GS; COMPONENTTYPE: 4; VAL1: LT8311EFE_PBF; VAL3: LT8311EFE_PBF
IC4 = TLP291: CDBNAME: TLP785_TS_1; COMMENT: Photo-Coupler(LED-Tr,80V50mA); COMP: TLP785_TS_1; COMPONENTTYPE: 4; INSTANCENAME: I580201; MAKER: Toshiba; SAVECOUNT: 1; UPDATEDATE: 2021/11/09; UPDATETIME: 20:28:41; USERCOMPTEXT3: TOSHIBA
IC9 = TLP291: CDBNAME: TLP785_TS_1; COMMENT: Photo-Coupler(LED-Tr,80V50mA); COMP: TLP785_TS_1; COMPONENTTYPE: 4; INSTANCENAME: I585285; MAKER: Toshiba; SAVECOUNT: 1; UPDATEDATE: 2021/11/09; UPDATETIME: 20:28:41; USERCOMPTEXT3: TOSHIBA
IC10 = OP_AMP_5PIN_2: CDBNAME: TLV7211AIDBVR_TI; COMP: TLV7211AIDBVR_TI; COMPONENTTYPE: 4; SAVECOUNT: 1; UPDATEDATE: 2021/11/09; UPDATETIME: 20:28:41; VAL1: TLV7211AIDBV; VAL3: TLV7211AIDBV
R37 = R: CDBNAME: Chip1608_GS_1; COMP: Chip1608_GS_1; COMPONENTTYPE: 4; SIZECODESMD: 1608; VAL1: 8.2k(F); VAL2: 100mW
R51 R53 = R: CDBNAME: Chip2012_GS_2; COMP: Chip2012_GS_2; COMPONENTTYPE: 4; SIZECODESMD: 2012; VAL1: 2.2k(F); VAL2: 400mW
R52 R54 = R: CDBNAME: Chip2012_GS_2; COMP: Chip2012_GS_2; COMPONENTTYPE: 4; SIZECODESMD: 2012; VAL1: 6.8k(F); VAL2: 400mW
R55 = R: CDBNAME: Chip1608_GS_1; COMP: Chip1608_GS_1; COMPONENTTYPE: 4; NOTMOUNT: NOT MOUNT; SIZECODESMD: 1608; VAL1: 1k(F); VAL2: 100mW
R57 = R: CDBNAME: Chip1608_GS_1; COMP: Chip1608_GS_1; COMPONENTTYPE: 4; SIZECODESMD: 1608; VAL1: 5.1k(F); VAL2: 100mW
R61 R62 = R: CDBNAME: Chip1608_GS_1; COMP: Chip1608_GS_1; COMPONENTTYPE: 4; SIZECODESMD: 1608; VAL1: 1.8k(F); VAL2: 100mW
R65 = R: CDBNAME: Chip1608_GS_1; COMP: Chip1608_GS_1; COMPONENTTYPE: 4; SIZECODESMD: 1608; VAL1: 51k(F); VAL2: 100mW
R66 = R: CDBNAME: Chip1608_GS_1; COMP: Chip1608_GS_1; COMPONENTTYPE: 4; SIZECODESMD: 1608; VAL1: 2.4k(F); VAL2: 100mW
R67 = R: CDBNAME: Chip1608_GS_1; COMP: Chip1608_GS_1; COMPONENTTYPE: 4; SIZECODESMD: 1608; VAL1: 330(F); VAL2: 100mW
R68 = R: CDBNAME: Chip1608_GS_1; COMP: Chip1608_GS_1; COMPONENTTYPE: 4; SIZECODESMD: 1608; VAL1: 3.3k(F); VAL2: 100mW
R92 = R: CDBNAME: Chip1608_GS_1; COMP: Chip1608_GS_1; COMPONENTTYPE: 4; SIZECODESMD: 1608; VAL1: 33k(F); VAL2: 100mW
R94 = R: CDBNAME: Chip1608_GS_1; COMP: Chip1608_GS_1; COMPONENTTYPE: 4; SIZECODESMD: 1608; VAL1: 2.2k(F); VAL2: 100mW
TP28 = TP: CDBNAME: TP_I_TH0.7_LC1.1_RC1.2_GS; COMP: TP_I_TH0.7_LC1.1_RC1.2_GS; COMPONENTTYPE: 4; NOTMOUNT: NOT MOUNT; VAL1: PAD; VAL3: PAD
U?#5 = WAKU_DEF100: AUTHOR: t5459927; COMPONENTTYPE: 2; DATE: 2021/11/29; DRAWINGNUMBER: RD175-SCHEMATIC-01; FUNCTION: Secondary Controller & Feed Back; REVISION: 01; SAVEAREA0: -45080,-4508,463680,304612; SHEETNUMBER: 5/5; TIME: 11:43:42; TITLE: 240W Active Clamp Forward / DC-DC Converter; UPDATEDATE: 2021/11/29; UPDATETIME: 13:14:17

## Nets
VIN: FB1.2 R114.2 R115.2 R121.1
I_11V: FB2.1 IC124.1(CTRL) IC124.5(VIN) R116.2 R117.2 R133.1
IGND: C2.2(1) C3.2(1) C6.1 C8.2 C11.2 C12.1 C13.1 C14.1 C15.1 C16.2 C17.1 C18.2 C61.1 C111.2 C112.1 C113.2 C121.1 C122.2 C123.1 C124.2 C125.1 C128.1 C129.1 CN3.1 IC1.7 IC2.10(PGND) IC2.11(AGND) IC2.15(SYNC) IC4.3(E) IC9.3(E) IC11.6(PRG2) IC11.7(PRG1) IC11.8(GND) IC11.14(GND) IC11.16(GND) IC11.EP IC121.5(GND) IC122.2(GND) IC122.3(A-IN) IC123.5 IC124.2(GND) J1.2 Q3.S R9.2 R13.2 R15.1 R22.2 R23.1 R28.1 R30.1 R31.1 R33.1 R34.2 R37.2 R112.2 R113.2 R122.2 R127.1 R129.1 R134.2 T2.1(OUT1) TP21.1 TP71.1 TP72.1
O_10V: C41.2 C81.2 FB3.1 IC3.6(INTVCC) IC3.7(VIN) IC10.2 R55.2 R64.2 R93.2 TP25.1
OGND: C31.2 C32.2 C33.2 C34.2 C35.2 C36.2(1) C41.1 C42.2 C43.2 C44.2 C49.1 C52.2 C53.2 C61.2 C81.1 C82.2 C83.1 CN5.1 D5.1(A) D8.1(A) D12.1(A) D13.1 D13.2 IC3.E IC4.2(A2) IC9.2(A2) IC10.5 Q8.S Q9.S Q10.S Q11.S R46.2 R47.2 R52.1 R54.1 R56.1 R58.1 R62.2 R63.1 R67.1 R92.1 R101.1 R102.1 R103.1 R104.1 T5.9 TP24.1 TP27.1 TP101.1 TP102.1 TP131.1 TP132.1
SIG001: D3.3 R15.2 T2.3(OUT3) TP23.1
SIG002: IC1.6 R25.1
SIG003: IC1.5 R24.1
SIG004: C12.2 D122.1(A) D123.1(A) IC2.16(UVLO) R21.2 R22.1
SIG005: IC2.13(COMP) IC4.4(C) R37.1
SIG006: IC9.4(C) R131.1
SIG7: IC2.9(OUT_B) R24.2
SIG007: IC3.5(FG) R41.2 R42.2
SIG008: C65.2 C67.2 D11.1(A) Q8.D Q9.D R51.2 T5.12 T5.13 TP8.1
SIG009: C66.2 D10.1(A) D13.3 L2.1 Q10.D Q11.D R48.1 R53.2 R61.2 T5.15 T5.16 TP11.1
SIG10: C112.2 IC11.10(SS)
SIG010: IC3.16(CG) R43.2 R44.2
SIG11: IC11.11(ISET) R113.1
SIG16: D3.2 R32.1 R34.1
SIG18: IC2.14(RT) R23.2
SIG19: C13.2 IC2.12(SS)
SIG22: C111.1 IC11.3(VIN) R114.1
SIG25: IC11.1(SW) L101.1
SIG27: C113.1 FB2.2 L101.2 R111.2 TP22.1
SIG32: IC11.9(VFB) R111.1 R112.1
SIG40: IC2.8(OUT_A) R25.2
SIG42: C14.2 IC2.7(VCC) R116.1
SIG45: C16.1 IC2.1(VIN) R26.2
SIG47: C17.2 IC2.2(RAMP) R27.2
SIG48: C11.1 R21.1 R26.1 R27.1 R115.1
SIG49: IC2.3(CS1) R28.2
SIG51: C15.2 IC2.6(REF) R29.2
SIG52: IC2.5(TIME) R29.1 R30.2
SIG54: C18.1 IC2.4(CS2) R31.2 R32.2
SIG57: D3.1 R33.2
SIG58: IC122.4(Y-OUT) R125.2 TP31.1
SIG60: D122.2(C) IC121.2(OUT1) IC122.6(C-IN) R124.2
SIG61: C122.1 C124.1 C126.2 C129.2 IC121.1(VDD) IC122.5(VCC) IC123.2 IC124.4(VOUT) R126.2 R128.2
SIG69: D123.2(C) IC123.1 R130.1 TP32.1
SIG70: C125.2 IC123.4 R125.1 R126.1 R127.2
SIG82: IC121.4(IN2) R133.2 R134.1
SIG85: C128.2 IC124.3(NOISE)
SIG87: C121.2 IC121.6(IN1) R121.2 R122.1
SIG90: C123.2 IC122.1(B-IN) R124.1
SIG93: C49.2 D10.2(C) D11.2(C) R105.2
SIG97: C53.1 FB3.2 Q7.3(E)
SIG100: C52.1 D6.2(C) Q7.2(C) R72.2
SIG107: C66.1 R47.1
SIG110: C65.1 R46.1
SIG115: Q8.G R41.1 R101.2 TP9.1
SIG121: D8.2(C) Q7.1(B) R72.1
SIG124: C83.2 IC9.1(A1) R94.1
SIG125: IC10.1 R94.2
SIG128: IC3.20(CSP) R61.1
SIG129: C45.2 TP28.1
SIG130: C82.1 IC10.3 R91.2 R92.2
SIG131: C43.1 IC3.10(COMP) R57.2
SIG133: C42.1 R57.1
SIG134: IC3.1(CSW) R53.1 R54.2
SIG135: IC3.12(TIMER) R58.2
SIG136: C46.2 IC3.11(FB) R65.1 R66.2
SIG137: IC3.18(CSN) R62.1
SIG138: C45.1 IC3.15(SYNC) R63.2
SIG139: IC3.3(FSW) R51.1 R52.2
SIG140: C44.1 IC3.14(SS)
SIG141: IC3.8(PMODEn) R55.1 R56.2
SIG142: IC3.13(PGOODn) R64.1 TP26.1
SIG152: C64.2 IC4.1(A1) R68.2
SIG153: C64.1 IC3.9(OPTO) R68.1
SIG161: D12.2(C) IC10.4 R93.1
SIG164: R66.1 R67.2
SIG177: IC1.3 R5.1
SIG178: Q2.G R5.2 R6.1 TP3.1
SIG179: C6.2 IC1.1 R117.1
SIG181: C5.1 IC1.2
SIG183: C67.1 R48.2
SIG193: C126.1 IC123.3 R128.1 R129.2 R130.2 R131.2
SIG211: R71.1 T5.10
SIG213: Q11.G R43.1 R103.2
SIG215: Q9.G R42.1 R102.2
SIG216: Q10.G R44.1 R104.2 TP12.1
SIG218: D5.2(C) D6.1(A) R71.2
TXP1: C1.1 C2.1(2) C3.1(2) C7.1 C8.1 C10.1 L1.2 Q1.3(E) R1.1 R2.1 R16.1 T5.1 T5.2
TXP2: T2.7(IN7) T5.4 T5.5
VOUT: C31.1 C32.1 C33.1 C34.1 C35.1 C36.1(2) C46.1 CN4.1 L2.2 R65.2 R91.1 R105.1
N560028: C1.2 Q1.1(B) R2.2 R3.2
N560054: FB1.1 Q1.2(C)
N560056: Q3.G R10.1 R11.2 R12.2 R13.1 TP6.1
N560076: C5.2 C9.1 IC1.4 Q2.S Q3.D R6.2 T2.8(IN8) TP5.1 TP41.1 TP42.1
N560174: D2.3 IC1.8 R10.2
N560196: C7.2 C10.2 Q2.D R16.2 TP2.1
N560216: D2.2 R11.1
N560310: CN1.1 L1.1 R1.2
N560402: CN2.1 J1.1 R3.1
N560656: D2.1 R12.1
N3881286: C9.2 R9.1

Not connected (* = marked no-connect by the designer): IC11 5(RUN) 12(FBO); IC121 3(OUT2); T2 2 4 5 6; T5 3 6 7 8 11 14

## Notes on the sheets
sheet 1
- Output-Over-Voltage
- 5.6[V]
sheet 2
- VOUT DC24V
- D5_not_mounted
sheet 3
- ON__:9.95[V]
- OFF_:9.85[V]
- 5[V]
- ON_:37.7[V]
- OFF_:37.3[V]
- Vth+:1.194[V]
- Vth-:1.182[V]
- 6pin(in)
- 1pin(in)
- 4pin(out)
sheet 4
- Vth=0.5(V)
- VREF=800(mV)
sheet 5
- VIN DC48V
